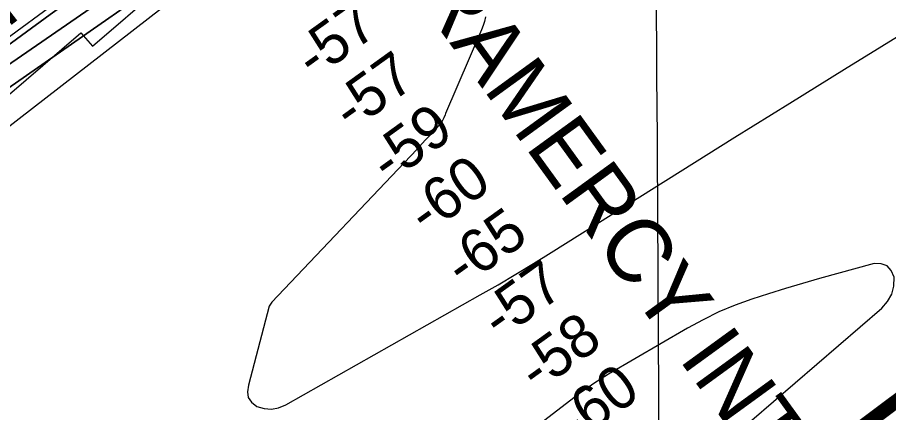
# Model space of a CAD drawing. Extents: x 3477039 to 3515015, y 546746 to 572297.
# Drawn here: x 3485493 to 3486854, y 560657 to 561273 of the extents above; entities that cross this region are included whole.
import ezdxf

# ---------------------------------------------------------------- set-up
doc = ezdxf.new("R2010")
doc.units = 0
for name, color, linetype in [('V-CHAN-NAID', 7, 'Continuous'), ('V-GRID-MAJR', 7, 'Continuous'), ('V-RIVR-IDEN', 7, 'Continuous'), ('V-RIVR-RANG', 7, 'Continuous'), ('V-RRAP-RVMT', 7, 'Continuous'), ('V-RRAP-RVMT-IDEN', 7, 'Continuous'), ('V-TOPO-DPTH', 7, 'Continuous'), ('V-TOPO-MAJR', 7, 'Continuous'), ('V-TOPO-MINR', 7, 'Continuous')]:
    doc.layers.add(name, color=color, linetype=linetype)

msp = doc.modelspace()

# ---------------------------------------------------------------- linework, layer by layer
at = {"layer": 'V-GRID-MAJR'}
msp.add_spline([(3486543.572, 552138.781), (3486509.202, 558197.813), (3486474.821, 564258.778), (3486440.44, 570319.761), (3486440.429, 570321.677)], degree=3, dxfattribs=at)
at = {"layer": 'V-RRAP-RVMT'}
msp.add_lwpolyline([(3485476.6000000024, 561150.2690000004), (3485591.7290000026, 561249.4490000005), (3485610.3020000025, 561228.4840000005), (3485716.7670000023, 561320.7620000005), (3485720.8250000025, 561316.0720000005), (3485831.9500000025, 561409.0720000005), (3485842.096000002, 561396.9800000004), (3485928.5640000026, 561468.5540000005), (3485947.0610000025, 561448.2620000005), (3486054.0250000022, 561540.9590000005), (3486076.1460000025, 561516.3480000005), (3486292.3840000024, 561702.2100000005), (3486300.6200000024, 561692.6860000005), (3486412.2850000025, 561782.7050000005), (3486435.9590000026, 561754.4920000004), (3486544.8570000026, 561844.8870000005), (3486636.4110000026, 561735.7770000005), (3486747.9430000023, 561828.8740000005), (3486787.8010000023, 561781.3710000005), (3486900.7550000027, 561873.9420000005)], dxfattribs=at)
at = {"layer": 'V-TOPO-DPTH'}
for points in [[(3487384.053615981, 562458.3326219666), (3486673.7201079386, 562008.4510709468), (3486666.569761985, 562003.9144071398), (3486659.4243031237, 561999.3700725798), (3486652.286174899, 561994.8142318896), (3486645.1529337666, 561990.2507204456), (3486633.3365290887, 561982.6777202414), (3486629.6862480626, 561980.3081898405), (3486628.4751035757, 561979.5097285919), (3486602.9226783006, 561962.5803151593), (3486588.94776222, 561953.2984556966), (3486574.9870271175, 561943.9953680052), (3486561.047563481, 561934.6604379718), (3486547.122280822, 561925.30427971), (3485899.5823469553, 561489.1598407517), (3485876.4991188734, 561473.5568103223), (3485853.4504820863, 561457.9030283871), (3485830.4537322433, 561442.1731191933), (3485807.4915736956, 561426.3924584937), (3485352.9536377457, 561112.9052102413)], [(3485352.9536377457, 561112.9052102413), (3485807.4915736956, 561426.3924584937), (3485830.4537322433, 561442.1731191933), (3485853.4504820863, 561457.9030283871), (3485876.4991188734, 561473.5568103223), (3485899.5823469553, 561489.1598407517), (3486547.122280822, 561925.30427971), (3486561.047563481, 561934.6604379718), (3486574.9870271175, 561943.9953680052), (3486588.94776222, 561953.2984556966), (3486602.9226783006, 561962.5803151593), (3486628.4751035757, 561979.5097285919), (3486629.6862480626, 561980.3081898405), (3486633.3365290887, 561982.6777202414), (3486645.1529337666, 561990.2507204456), (3486652.286174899, 561994.8142318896), (3486659.4243031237, 561999.3700725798), (3486666.569761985, 562003.9144071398), (3486673.7201079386, 562008.4510709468), (3487384.053615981, 562458.3326219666)], [(3487172.022261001, 562280.6930445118), (3486707.518902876, 561985.4817452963), (3486679.9119905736, 561967.8972470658), (3486652.328834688, 561950.2756454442), (3486624.7813134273, 561932.5983887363), (3486597.257548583, 561914.884028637), (3486460.526636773, 561826.6883559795), (3486364.820102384, 561764.5975873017), (3486269.3333790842, 561702.1725141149), (3486174.1763724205, 561639.2459841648), (3486079.239176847, 561575.9851497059), (3485892.7303300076, 561450.9964345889), (3485881.140612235, 561443.1846119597), (3485869.5789997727, 561435.3316480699), (3485858.059545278, 561427.4169722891), (3485846.568196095, 561419.4611552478), (3485436.217441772, 561133.7365415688)], [(3485436.217441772, 561133.7365415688), (3485846.568196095, 561419.4611552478), (3485858.059545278, 561427.4169722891), (3485869.5789997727, 561435.3316480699), (3485881.140612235, 561443.1846119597), (3485892.7303300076, 561450.9964345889), (3486079.239176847, 561575.9851497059), (3486174.1763724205, 561639.2459841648), (3486269.3333790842, 561702.1725141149), (3486364.820102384, 561764.5975873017), (3486460.526636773, 561826.6883559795), (3486597.257548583, 561914.884028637), (3486624.7813134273, 561932.5983887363), (3486652.328834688, 561950.2756454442), (3486679.9119905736, 561967.8972470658), (3486707.518902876, 561985.4817452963), (3487172.022261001, 562280.6930445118)], [(3484980.8436918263, 560866.3028772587), (3485543.993146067, 561277.7964146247), (3485592.0954990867, 561312.6788219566), (3485640.3639964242, 561347.3280048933), (3485688.8817102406, 561381.6273512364), (3485737.5655683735, 561415.6934731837), (3485763.7222217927, 561433.8558885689), (3485799.4943120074, 561458.6047315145), (3485835.3223146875, 561483.2720675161), (3485871.2341860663, 561507.8171431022), (3485907.201969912, 561532.2807117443), (3485935.3853616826, 561551.3795397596), (3485985.5263397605, 561585.2725151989), (3486035.720067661, 561619.0869911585), (3486085.9929202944, 561652.7837178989), (3486136.318522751, 561686.4019451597), (3486587.7983757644, 561987.2323140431), (3486601.0953243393, 561996.0372195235), (3486614.4256995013, 562004.7909014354), (3486627.8062145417, 562013.4677479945), (3486641.220156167, 562022.0933709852), (3486768.797291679, 562103.612054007), (3486845.97795632, 562153.0315147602), (3486923.096066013, 562202.5481972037)], [(3484980.8436918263, 560866.3028772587), (3485543.993146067, 561277.7964146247), (3485592.0954990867, 561312.6788219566), (3485640.3639964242, 561347.3280048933), (3485688.8817102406, 561381.6273512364), (3485737.5655683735, 561415.6934731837), (3485763.7222217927, 561433.8558885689), (3485799.4943120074, 561458.6047315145), (3485835.3223146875, 561483.2720675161), (3485871.2341860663, 561507.8171431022), (3485907.201969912, 561532.2807117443), (3485935.3853616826, 561551.3795397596), (3485985.5263397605, 561585.2725151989), (3486035.720067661, 561619.0869911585), (3486085.9929202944, 561652.7837178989), (3486136.318522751, 561686.4019451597), (3486587.7983757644, 561987.2323140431), (3486601.0953243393, 561996.0372195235), (3486614.4256995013, 562004.7909014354), (3486627.8062145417, 562013.4677479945), (3486641.220156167, 562022.0933709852), (3486768.797291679, 562103.612054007), (3486845.97795632, 562153.0315147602), (3486923.096066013, 562202.5481972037)]]:
    msp.add_lwpolyline(points, dxfattribs=at)
at = {"layer": 'V-TOPO-MAJR'}
msp.add_lwpolyline([(3486888.2054187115, 562058.5755411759), (3486816.689061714, 562012.2463538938), (3486733.5940860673, 561958.7208390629), (3486703.4957316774, 561939.351965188), (3486673.3859071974, 561920.0009560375), (3486643.2588775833, 561900.6767439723), (3486613.120377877, 561881.3703966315), (3485927.1926311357, 561442.4038666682), (3485920.0417560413, 561437.8007199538), (3485912.9073715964, 561433.1723016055), (3485905.7977231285, 561428.5059758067), (3485898.704565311, 561423.8143783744), (3485886.2859211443, 561415.5527744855), (3485884.551776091, 561414.3804780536), (3485883.691733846, 561413.7840945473), (3485882.83520674, 561413.1825933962), (3485866.673935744, 561401.7255413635), (3485857.7807130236, 561395.3359450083), (3485848.9425405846, 561388.8720692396), (3485840.1869435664, 561382.2967743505), (3485831.48639683, 561375.6472000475), (3485040.846399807, 560763.4133652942)], dxfattribs=at)
at = {"layer": 'V-TOPO-MINR'}
for points in [[(3487384.053615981, 562458.3326219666), (3486673.7201079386, 562008.4510709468), (3486666.569761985, 562003.9144071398), (3486659.4243031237, 561999.3700725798), (3486652.286174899, 561994.8142318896), (3486645.1529337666, 561990.2507204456), (3486633.3365290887, 561982.6777202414), (3486629.6862480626, 561980.3081898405), (3486628.4751035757, 561979.5097285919), (3486602.9226783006, 561962.5803151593), (3486588.94776222, 561953.2984556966), (3486574.9870271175, 561943.9953680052), (3486561.047563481, 561934.6604379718), (3486547.122280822, 561925.30427971), (3485899.5823469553, 561489.1598407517), (3485876.4991188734, 561473.5568103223), (3485853.4504820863, 561457.9030283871), (3485830.4537322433, 561442.1731191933), (3485807.4915736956, 561426.3924584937), (3485352.9536377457, 561112.9052102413)], [(3487172.022261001, 562280.6930445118), (3486707.518902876, 561985.4817452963), (3486679.9119905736, 561967.8972470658), (3486652.328834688, 561950.2756454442), (3486624.7813134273, 561932.5983887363), (3486597.257548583, 561914.884028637), (3486460.526636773, 561826.6883559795), (3486364.820102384, 561764.5975873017), (3486269.3333790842, 561702.1725141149), (3486174.1763724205, 561639.2459841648), (3486079.239176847, 561575.9851497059), (3485892.7303300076, 561450.9964345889), (3485881.140612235, 561443.1846119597), (3485869.5789997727, 561435.3316480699), (3485858.059545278, 561427.4169722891), (3485846.568196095, 561419.4611552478), (3485436.217441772, 561133.7365415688)], [(3486923.096066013, 562202.5481972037), (3486845.97795632, 562153.0315147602), (3486768.797291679, 562103.612054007), (3486641.220156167, 562022.0933709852), (3486627.8062145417, 562013.4677479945), (3486614.4256995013, 562004.7909014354), (3486601.0953243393, 561996.0372195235), (3486587.7983757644, 561987.2323140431), (3486136.318522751, 561686.4019451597), (3486085.9929202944, 561652.7837178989), (3486035.720067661, 561619.0869911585), (3485985.5263397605, 561585.2725151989), (3485935.3853616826, 561551.3795397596), (3485907.201969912, 561532.2807117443), (3485871.2341860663, 561507.8171431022), (3485835.3223146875, 561483.2720675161), (3485799.4943120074, 561458.6047315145), (3485763.7222217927, 561433.8558885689), (3485737.5655683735, 561415.6934731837), (3485688.8817102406, 561381.6273512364), (3485640.3639964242, 561347.3280048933), (3485592.0954990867, 561312.6788219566), (3485543.993146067, 561277.7964146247), (3484980.8436918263, 560866.3028772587)], [(3486868.999731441, 562184.73186865), (3486645.275508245, 562042.1702061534), (3486625.6220450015, 562029.5628314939), (3486606.020007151, 562016.8765224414), (3486586.4951073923, 562004.0718117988), (3486567.0216330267, 561991.1881667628), (3485905.7348810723, 561550.798203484), (3485892.360640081, 561541.8445052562), (3485879.0156605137, 561532.8476306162), (3485865.71457308, 561523.785991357), (3485852.442747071, 561514.6811756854), (3485828.317512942, 561498.0442624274), (3485825.9489110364, 561496.3983196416), (3485824.7693471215, 561495.5685831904), (3485823.592151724, 561494.7354642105), (3485801.761451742, 561479.2150785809), (3485789.6908934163, 561470.5912635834), (3485777.647281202, 561461.9301621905), (3485765.6440881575, 561453.2131312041), (3485753.6678412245, 561444.4588138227), (3484982.249396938, 560877.8148738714)], [(3486224.2118814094, 561274.0785600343), (3486222.6538009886, 561267.1944904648), (3486220.5206275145, 561260.4663704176), (3486218.004058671, 561253.8422167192), (3486161.9695574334, 561123.2784982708), (3486161.0402550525, 561121.1028578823), (3486159.199130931, 561116.7441931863), (3486157.2736963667, 561112.4439328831), (3486154.7662645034, 561108.5160053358), (3486153.272445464, 561106.7053137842), (3486134.50677927, 561086.2504700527), (3486130.140093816, 561081.5158356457), (3486125.756862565, 561076.796650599), (3486121.3488126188, 561072.1006395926), (3486116.924216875, 561067.4200779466), (3485890.3651628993, 560829.01644912), (3485886.0510065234, 560822.3719842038), (3485853.901584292, 560699.3461751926), (3485852.2641016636, 560689.1532086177), (3485853.402099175, 560680.0353760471), (3485858.7033168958, 560672.5302444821), (3485866.780014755, 560666.1002469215), (3485878.3030029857, 560662.9562010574), (3485889.715138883, 560661.94518754), (3485900.960996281, 560664.133722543), (3485912.0960013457, 560668.4552898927), (3486215.8660051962, 560840.0553671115), (3486243.9124689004, 560856.1614948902), (3486271.802780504, 560872.5294411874), (3486299.4588639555, 560889.2901152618), (3486326.958795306, 560906.3126078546), (3486443.0113657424, 560979.2892866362), (3486528.4847590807, 561032.8933289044), (3486614.0439446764, 561086.3597136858), (3486699.73181866, 561139.6196122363), (3486785.5054849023, 561192.7418532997), (3487018.428182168, 561336.6096747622)], [(3486852.119129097, 560885.7289552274), (3486842.7878940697, 560888.8915729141), (3486831.4808130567, 560889.1501967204), (3486746.1189987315, 560865.6277940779), (3486719.54167447, 560858.0839480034), (3486693.046477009, 560850.2693370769), (3486666.6744697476, 560842.0485788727), (3486640.384589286, 560833.5570558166), (3486614.511872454, 560824.0744880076), (3486589.1089643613, 560813.5508308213), (3486564.410769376, 560801.4655395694), (3486540.18238313, 560788.3391589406), (3486416.7015203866, 560716.3686002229), (3486405.0514384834, 560709.2879348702), (3486393.5869957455, 560701.9294270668), (3486382.4010117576, 560694.1541555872), (3486371.4006669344, 560686.1010416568), (3486267.338098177, 560606.9365120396)], [(3486572.899476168, 560586.3245928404), (3486843.7896158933, 560819.5088824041), (3486852.728623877, 560829.9310966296), (3486859.2865700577, 560841.2947401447), (3486862.272923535, 560854.0705275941), (3486862.8782152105, 560867.7877443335), (3486858.4865951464, 560878.2103467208), (3486852.119129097, 560885.7289552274)]]:
    msp.add_lwpolyline(points, dxfattribs=at)

# ---------------------------------------------------------------- texts
at = {"layer": 'V-CHAN-NAID'}
msp.add_text('GRAMERCY INTAKE (146.6)', height=100.00000200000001, rotation=305.96759199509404, dxfattribs=at).set_placement((3486049.4246556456, 561396.1467468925))
at = {"layer": 'V-RIVR-IDEN'}
msp.add_text('E', height=199.99959800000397, rotation=36.77180055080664, dxfattribs=at).set_placement((3486895.4371710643, 560460.1250533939))
at = {"layer": 'V-RIVR-RANG'}
for s, p in [('-57', (3485956.0076996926, 561175.6620317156)), ('-57', (3486014.1446996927, 561094.2980317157)), ('-59', (3486072.7197758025, 561013.248689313)), ('-60', (3486131.713742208, 560932.5002238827)), ('-65', (3486189.208017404, 560850.6755729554)), ('-57', (3486246.6926996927, 560768.8430317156)), ('-58', (3486304.625050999, 560687.3320383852)), ('-60', (3486364.2617422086, 560607.0452238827))]:
    msp.add_text(s, height=67.00000000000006, rotation=35.6886111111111, dxfattribs=at).set_placement(p)
at = {"layer": 'V-RRAP-RVMT-IDEN'}
msp.add_text('ANGELINA', height=99.99980199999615, rotation=37.98560021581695, dxfattribs=at).set_placement((3485088.531684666, 560953.1235839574))

doc.saveas('drawing.dxf')
